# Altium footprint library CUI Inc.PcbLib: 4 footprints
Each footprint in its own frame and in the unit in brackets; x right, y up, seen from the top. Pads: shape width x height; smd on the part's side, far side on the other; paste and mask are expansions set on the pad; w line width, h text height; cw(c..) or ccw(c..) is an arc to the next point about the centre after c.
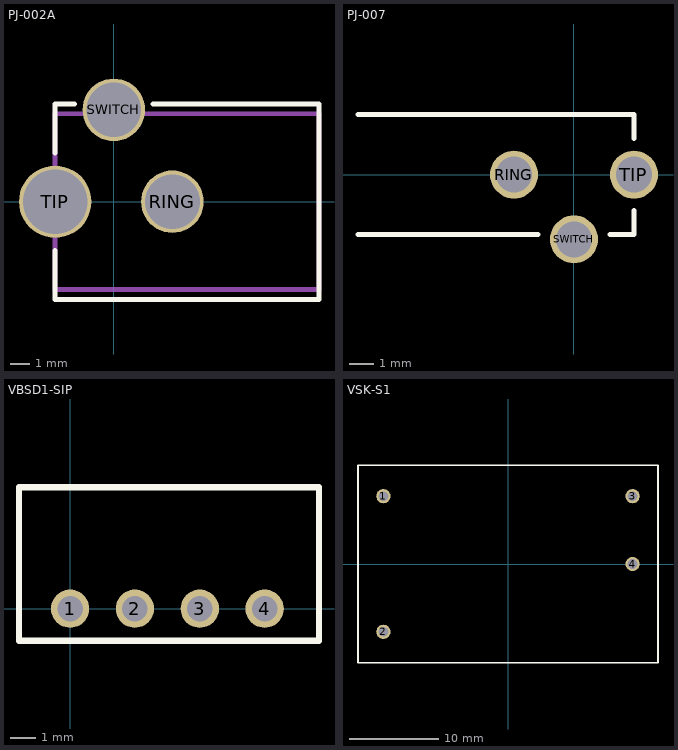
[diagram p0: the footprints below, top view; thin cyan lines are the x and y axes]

## PJ-002A [mm] "DC Power Jack - Barrel Type"
height 11
pads (3):
  round 3.2 hole 2.8: RING(3,0) SWITCH(0,4.7)
  round 3.7 hole 3.3: TIP(-3,0)
Top Overlay:
  lines w0.254: -3,-2.5 -3,-5 10.5,-5 10.5,5 2,5 ; -3,2.5 -3,5 -2,5
Mechanical 13:
  lines w0.254: -3,-4.5 10.5,-4.5 10.5,4.5 -3,4.5 -3,-4.5
3D body: height 11, standoff 0, extent -3,-4.5 10.5,4.5

## PJ-007 [mm] "Power Jack 1.3mm ID, 3.5mm OD"
height 7.4
pads (3):
  round 2 hole 1.5: RING(-2.5,0) SWITCH(0,-2.7) TIP(2.5,0)
Top Overlay:
  lines w0.2: -9,-2.5 -1.5,-2.5 ; -9,2.5 2.5,2.5 2.5,1.5 ; 1.5,-2.5 2.5,-2.5 2.5,-1.5
3D body: height 7.4, standoff 0, extent -9,-2.5 2.5,2.5

## VBSD1-SIP [mm] "Potted DC-DC converter"
pads (4):
  round 1.5 hole 1: 1(0,0) 2(2.54,0) 3(5.08,0) 4(7.62,0)
Top Overlay:
  lines w0.254: -2,-1.25 -2,4.75 9.75,4.75 9.75,-1.25 -2,-1.25
3D body: height 10, standoff 0, extent -2,-1.25 9.75,4.75

## VSK-S1 [mm] "AC-DC converter"
height 18
pads (4):
  round 1.6 hole 1.1: 1(-14,7.62) 2(-14,-7.62) 3(14,7.62) 4(14,0)
Top Overlay:
  lines w0.2: -16.85,-11.1 -16.85,11.1 16.85,11.1 16.85,-11.1 -16.85,-11.1
3D body: height 18, standoff 0, extent -16.85,-11.1 16.85,11.1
